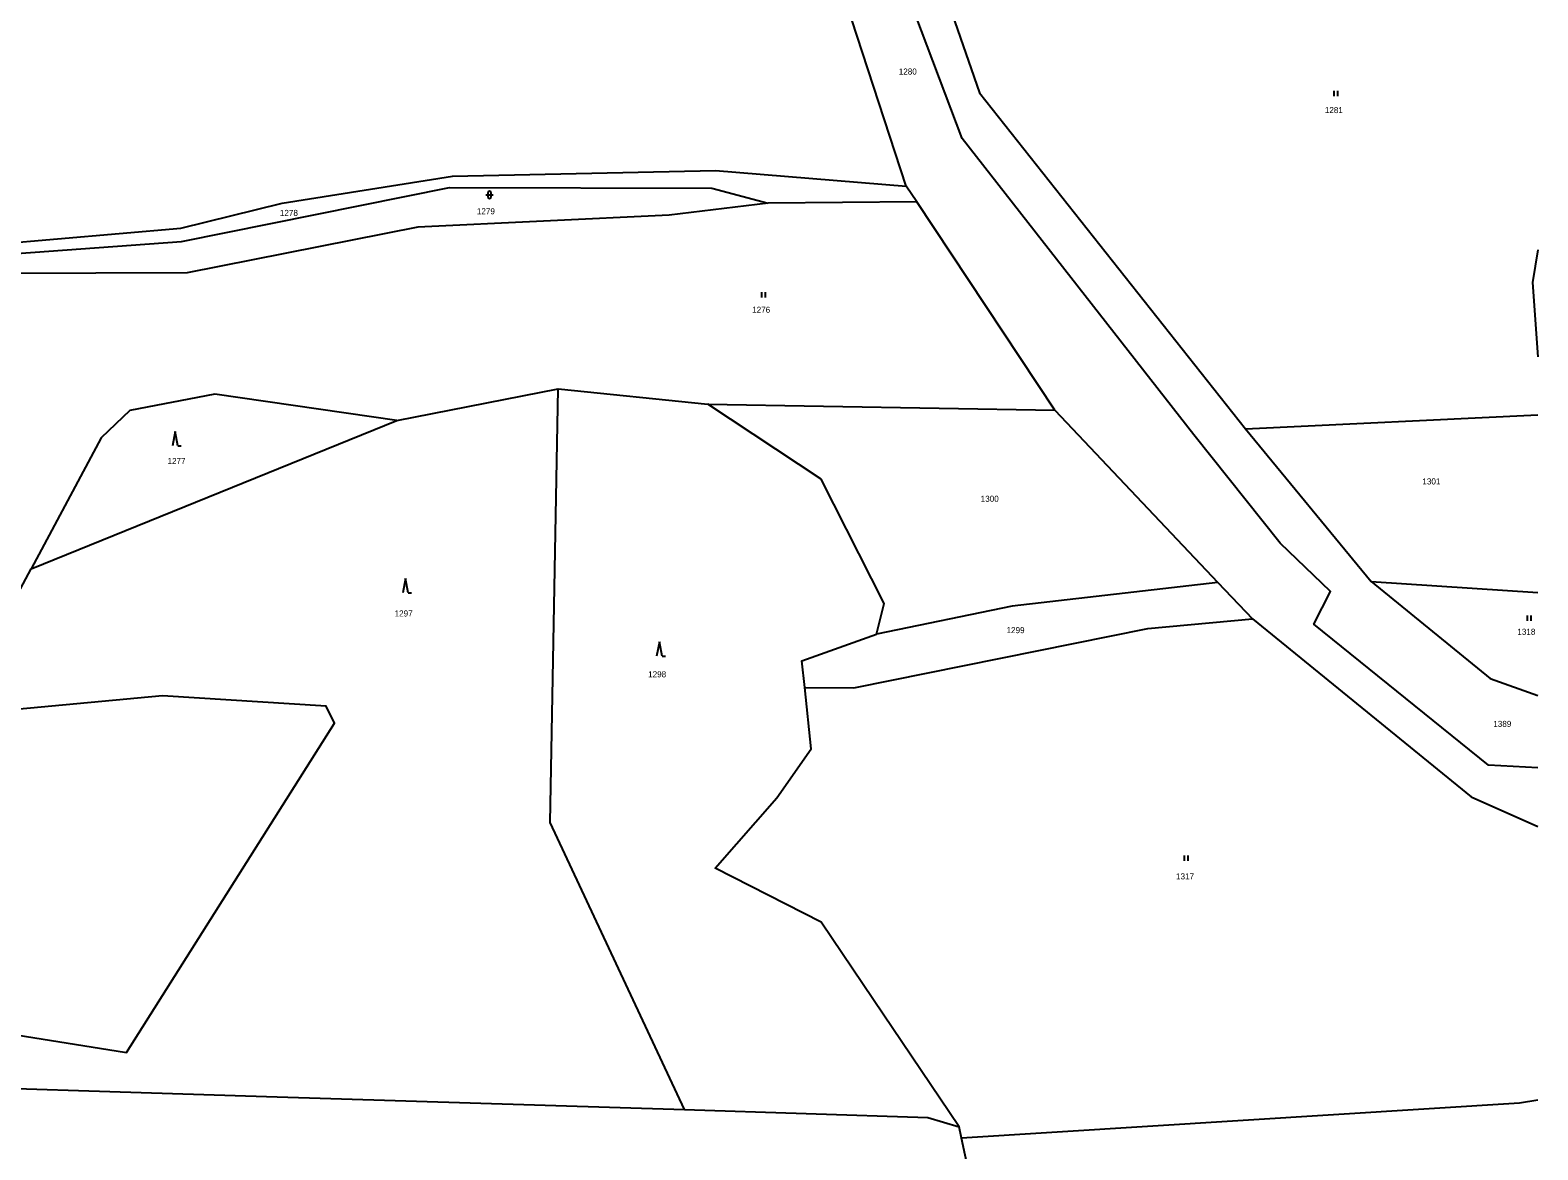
# Model space of a CAD drawing. Extents: x -520431 to -517205, y -1075927 to -1074013.
# Drawn here: x -517627.2 to -517205.1, y -1075018.9 to -1074705.2 of the extents above; entities that cross this region are included whole.
import ezdxf

# ---------------------------------------------------------------- set-up
doc = ezdxf.new("R2010")
doc.units = 0
for name, color, linetype in [('Hranice parcel', 7, 'Continuous'), ('Parcelní čísla', 7, 'Continuous'), ('Značky kultur', 7, 'Continuous')]:
    doc.layers.add(name, color=color, linetype=linetype)

msp = doc.modelspace()

# ---------------------------------------------------------------- linework, layer by layer
at = {"layer": 'Hranice parcel'}
for p, q in [((-517378.96, -1074753.37), (-517381.92, -1074748.9)), ((-517378.96, -1074753.37), (-517420.59, -1074753.71)), ((-517340.35, -1074811.69), (-517378.96, -1074753.37)), ((-517524.55, -1074814.61), (-517479.36, -1074805.73)), ((-517479.36, -1074805.73), (-517437.45, -1074809.97)), ((-517437.45, -1074809.97), (-517340.35, -1074811.69)), ((-517340.35, -1074811.69), (-517294.66, -1074859.95)), ((-517626.95, -1074856.18), (-517524.55, -1074814.61)), ((-517286.97, -1074816.94), (-517205.09, -1074813.05)), ((-517286.97, -1074816.94), (-517251.78, -1074859.65)), ((-517644.8, -1074889.6), (-517626.95, -1074856.18)), ((-517294.66, -1074859.95), (-517285.02, -1074870.13)), ((-517251.78, -1074859.65), (-517205.09, -1074862.76)), ((-517366.43, -1075015.6), (-517367.11, -1075012.43))]:
    msp.add_line(p, q, dxfattribs=at)
for points in [[(-517205.09, -1074911.93), (-517218.93, -1074911.17), (-517267.83, -1074871.62), (-517263.14, -1074862.5), (-517277.22, -1074848.96), (-517301.45, -1074818.64), (-517366.28, -1074735.57), (-517393.83, -1074662.56), (-517407.88, -1074631.04), (-517419.96, -1074617.3), (-517498.11, -1074559.8), (-517535.04, -1074532.01)], [(-517381.92, -1074748.9), (-517412.48, -1074655.42), (-517441.76, -1074654.92), (-517561.57, -1074569.26)], [(-517379.03, -1074671.93), (-517361.39, -1074722.76), (-517286.97, -1074816.94)], [(-517660, -1074768.08), (-517654.16, -1074766.7), (-517584.99, -1074760.67), (-517556.63, -1074753.66), (-517508.94, -1074746.11), (-517435.3, -1074744.53), (-517381.92, -1074748.9)], [(-517660.04, -1074773.47), (-517650.26, -1074769.19), (-517584.81, -1074764.44), (-517509.78, -1074749.3), (-517436.37, -1074749.53), (-517420.59, -1074753.71)], [(-517420.59, -1074753.71), (-517448.28, -1074757.11), (-517518.68, -1074760.42), (-517583.27, -1074773.25), (-517660.04, -1074773.47)], [(-517205.09, -1074766.79), (-517206.59, -1074775.91), (-517205.09, -1074796.73)], [(-517524.55, -1074814.61), (-517575.46, -1074807.19), (-517599.26, -1074811.78), (-517607.32, -1074819.43), (-517626.95, -1074856.18)], [(-517444, -1075007.65), (-517481.64, -1074927.22), (-517479.36, -1074805.73)], [(-517390.23, -1074874.41), (-517388.08, -1074865.82), (-517405.7, -1074831), (-517437.45, -1074809.97)], [(-517294.66, -1074859.95), (-517352.29, -1074866.59), (-517390.23, -1074874.41)], [(-517251.78, -1074859.65), (-517218.46, -1074886.83), (-517205.09, -1074891.6)], [(-517410.35, -1074889.43), (-517396.6, -1074889.47), (-517314.25, -1074872.86), (-517285.02, -1074870.13)], [(-517285.02, -1074870.13), (-517223.72, -1074919.98), (-517205.09, -1074928.34)], [(-517410.35, -1074889.43), (-517411.14, -1074881.92), (-517390.23, -1074874.41)], [(-517678.03, -1075000.2), (-517657.48, -1074982.54), (-517600.21, -1074991.68), (-517541.97, -1074899.41), (-517544.37, -1074894.62), (-517590.13, -1074891.7), (-517631.12, -1074895.59), (-517644.8, -1074889.6)], [(-517367.11, -1075012.43), (-517391.05, -1074976.91), (-517405.7, -1074955.18), (-517435.45, -1074939.96), (-517418.2, -1074920.28), (-517408.56, -1074906.53), (-517410.35, -1074889.43)], [(-517678.03, -1075000.2), (-517561.02, -1075003.93), (-517444, -1075007.65)], [(-517205.09, -1075004.98), (-517210.2, -1075005.81), (-517366.43, -1075015.6)], [(-517444, -1075007.65), (-517375.89, -1075009.82), (-517367.11, -1075012.43)], [(-517357.95, -1075033.09), (-517364.39, -1075025.15), (-517366.43, -1075015.6)]]:
    msp.add_lwpolyline(points, dxfattribs=at)
at = {"layer": 'Značky kultur'}
for p, q in [((-517262.08, -1074723.7), (-517262.08, -1074722.2)), ((-517261.08, -1074723.7), (-517261.08, -1074722.2)), ((-517499.61, -1074751.36), (-517497.61, -1074751.36)), ((-517499.11, -1074750.86), (-517499.11, -1074751.86)), ((-517498.11, -1074751.86), (-517498.11, -1074750.86)), ((-517422.31, -1074780.12), (-517422.31, -1074778.62)), ((-517421.31, -1074780.12), (-517421.31, -1074778.62)), ((-517586.64, -1074817.71), (-517587.39, -1074821.71)), ((-517585.89, -1074821.71), (-517586.64, -1074817.71)), ((-517585.89, -1074821.71), (-517584.89, -1074821.71)), ((-517522.15, -1074858.88), (-517522.9, -1074862.88)), ((-517521.4, -1074862.88), (-517522.15, -1074858.88)), ((-517521.4, -1074862.88), (-517520.4, -1074862.88)), ((-517207.97, -1074870.71), (-517207.97, -1074869.21)), ((-517206.97, -1074870.71), (-517206.97, -1074869.21)), ((-517451.05, -1074876.59), (-517451.8, -1074880.59)), ((-517450.3, -1074880.59), (-517451.05, -1074876.59)), ((-517450.3, -1074880.59), (-517449.3, -1074880.59)), ((-517304.01, -1074937.96), (-517304.01, -1074936.46)), ((-517303.01, -1074937.96), (-517303.01, -1074936.46))]:
    msp.add_line(p, q, dxfattribs=at)
for centre, start, end in [((-517498.61, -1074750.86), 0, 180), ((-517498.61, -1074751.86), 180, 359.9879)]:
    msp.add_arc(centre, 0.5, start, end, dxfattribs=at)

# ---------------------------------------------------------------- texts
at = {"layer": 'Parcelní čísla'}
for s, p in [('1280', (-517384.02, -1074717.68)), ('1281', (-517264.73, -1074728.48)), ('1278', (-517557.29, -1074757.28)), ('1279', (-517502.14, -1074756.82)), ('1276', (-517425.07, -1074784.42)), ('1277', (-517588.75, -1074826.78)), ('1301', (-517237.42, -1074832.51)), ('1300', (-517361.08, -1074837.37)), ('1297', (-517525.17, -1074869.5)), ('1299', (-517353.85, -1074874.17)), ('1318', (-517210.83, -1074874.64)), ('1298', (-517454.19, -1074886.54)), ('1389', (-517217.57, -1074900.44)), ('1317', (-517306.39, -1074943.15))]:
    msp.add_text(s, height=1.7, dxfattribs=at).set_placement(p)

doc.saveas('drawing.dxf')
